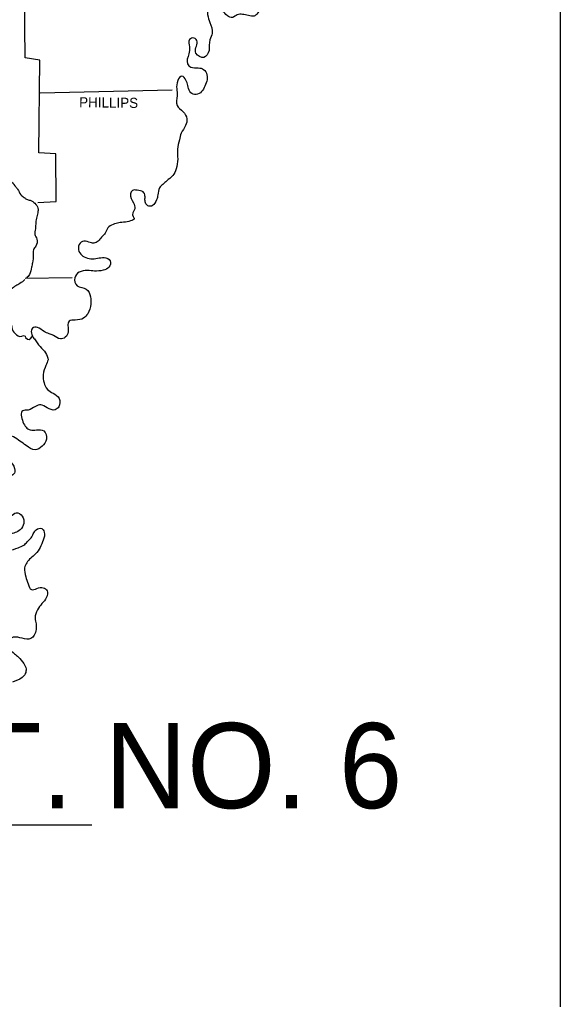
# Model space of a CAD drawing. Extents: x 22866 to 28196, y 1324810 to 1328105.
# Drawn here: x 26814.2 to 27045.6, y 1326588.3 to 1327007.4 of the extents above; entities that cross this region are included whole.
import ezdxf

# ---------------------------------------------------------------- set-up
doc = ezdxf.new("R2010")
doc.units = 0
for name, color, linetype in [('Default', 7, 'Continuous'), ('Level 2', 7, 'Continuous'), ('R_Border', 7, 'Continuous'), ('R_Draft', 7, 'Continuous')]:
    doc.layers.add(name, color=color, linetype=linetype)

msp = doc.modelspace()

# ---------------------------------------------------------------- linework, layer by layer
at = {"layer": 'Default'}
msp.add_line((26431.16, 1326662.93), (26845.06, 1326662.93), dxfattribs=at)
at = {"layer": 'R_Border'}
msp.add_line((27045.59, 1325448.4), (27045.59, 1327502.95), dxfattribs=at)
at = {"layer": 'R_Draft'}
msp.add_line((26816.65, 1326896.78), (26836.65, 1326897.08), dxfattribs=at)
for points in [[(26822.05, 1326929.08), (26829.85, 1326929.58), (26829.75, 1326949.88), (26822.45, 1326950.38), (26822.85, 1326990.08), (26816.55, 1326990.98), (26816.35, 1327017.68), (26901.65, 1327018.28)], [(26823.05, 1326975.98), (26879.45, 1326977.38)], [(26814.25, 1326871.88), (26815.15, 1326871.95), (26815.82, 1326872.25), (26816.57, 1326872.01), (26816.79, 1326871.36), (26817.52, 1326870.66), (26818.36, 1326870.56), (26818.96, 1326871.05), (26819.61, 1326871.88)]]:
    msp.add_lwpolyline(points, dxfattribs=at)
for points in [[(26938.75, 1327093.18), (26939.15, 1327090.28), (26937.45, 1327087.18), (26936.85, 1327084.08), (26937.15, 1327080.98), (26933.95, 1327079.28), (26931.15, 1327077.28), (26932.75, 1327074.88), (26935.75, 1327072.68), (26938.75, 1327070.98), (26940.65, 1327069.28), (26941.15, 1327065.18), (26941.65, 1327062.58), (26942.65, 1327058.98), (26943.05, 1327056.48), (26941.25, 1327053.48), (26939.15, 1327052.88), (26936.95, 1327053.58), (26934.35, 1327053.78), (26932.25, 1327051.78), (26930.75, 1327048.98), (26929.25, 1327046.18), (26928.15, 1327043.78), (26927.05, 1327041.18), (26924.85, 1327038.18), (26922.15, 1327037.68), (26918.95, 1327036.88), (26917.05, 1327034.68), (26917.35, 1327030.98), (26919.15, 1327028.48), (26920.55, 1327025.38), (26921.55, 1327022.68), (26921.05, 1327019.28), (26919.65, 1327016.78), (26917.85, 1327015.28), (26917.05, 1327012.08), (26915.75, 1327009.68), (26914.55, 1327008.88), (26912.15, 1327009.08), (26909.55, 1327009.58), (26907.35, 1327009.38), (26905.25, 1327008.28), (26903.15, 1327008.98), (26900.95, 1327011.38), (26899.15, 1327013.18), (26897.15, 1327013.88), (26895.05, 1327012.78), (26894.65, 1327009.48), (26895.65, 1327006.08), (26896.55, 1327001.48), (26895.65, 1326998.68), (26895.35, 1326994.08)], [(26895.35, 1326994.08), (26893.05, 1326991.18), (26889.65, 1326992.98), (26889.65, 1326995.38), (26890.15, 1326997.88), (26888.95, 1326999.48), (26886.85, 1326998.78), (26886.85, 1326995.68), (26886.65, 1326992.68), (26886.05, 1326988.38), (26887.45, 1326987.08), (26890.65, 1326986.68), (26892.95, 1326986.08), (26894.35, 1326983.78), (26894.25, 1326980.98), (26893.15, 1326978.28), (26891.55, 1326976.08), (26889.05, 1326975.28), (26887.05, 1326976.58), (26886.25, 1326979.18), (26885.35, 1326981.48), (26883.65, 1326983.18), (26881.85, 1326981.28), (26881.45, 1326977.78), (26881.55, 1326974.78), (26881.55, 1326970.68), (26884.15, 1326967.98), (26885.75, 1326964.88), (26885.25, 1326962.08), (26883.35, 1326958.78), (26882.55, 1326955.88), (26881.75, 1326951.98), (26881.85, 1326947.68), (26881.15, 1326943.48), (26879.75, 1326940.68), (26877.15, 1326938.38), (26875.45, 1326936.88), (26874.05, 1326935.38), (26873.35, 1326932.38), (26872.85, 1326930.28), (26870.95, 1326927.78), (26869.45, 1326927.58), (26868.25, 1326928.58), (26867.85, 1326930.28), (26867.85, 1326931.98), (26867.05, 1326933.68), (26864.55, 1326934.38), (26862.55, 1326934.28), (26861.65, 1326932.88), (26862.95, 1326928.98), (26863.45, 1326926.48), (26862.75, 1326923.08), (26863.15, 1326922.68), (26859.55, 1326920.78), (26856.65, 1326920.48), (26854.25, 1326919.78), (26851.95, 1326918.28), (26850.85, 1326916.08), (26849.25, 1326914.28), (26847.85, 1326912.58), (26845.95, 1326911.78), (26843.85, 1326912.18), (26841.05, 1326912.48), (26839.45, 1326910.48), (26839.95, 1326907.58), (26841.85, 1326905.88), (26844.65, 1326905.08), (26847.55, 1326905.28), (26850.35, 1326905.58), (26852.95, 1326904.18), (26852.45, 1326901.48), (26849.95, 1326900.18), (26846.25, 1326899.78), (26843.25, 1326900.08), (26839.65, 1326899.28), (26837.85, 1326896.98), (26838.85, 1326893.48), (26842.75, 1326892.08), (26844.55, 1326888.78), (26844.65, 1326885.68), (26843.35, 1326881.58), (26841.55, 1326879.68), (26838.05, 1326878.88), (26835.35, 1326878.38), (26834.95, 1326873.78), (26833.75, 1326871.48), (26831.65, 1326870.78), (26828.65, 1326872.28), (26826.85, 1326872.98), (26824.65, 1326873.98), (26821.85, 1326875.68), (26819.75, 1326875.38), (26820.35, 1326870.98), (26820.55, 1326870.78), (26822.95, 1326867.48), (26825.35, 1326864.88), (26826.45, 1326861.78)], [(26791.75, 1326961.88), (26792.05, 1326957.78), (26794.45, 1326957.18), (26795.45, 1326956.08), (26795.95, 1326953.78), (26797.65, 1326952.78), (26799.95, 1326951.38), (26801.35, 1326950.38), (26802.35, 1326948.78), (26802.95, 1326946.18), (26804.55, 1326944.48), (26806.75, 1326943.68), (26808.35, 1326941.78), (26809.35, 1326939.08), (26810.95, 1326937.88), (26812.55, 1326935.78), (26813.35, 1326934.88), (26814.75, 1326932.48), (26816.15, 1326931.28), (26817.15, 1326930.58), (26818.75, 1326930.08), (26820.75, 1326928.78), (26822.05, 1326926.78), (26822.05, 1326925.28), (26821.55, 1326922.98), (26821.15, 1326920.58), (26820.95, 1326917.88), (26820.75, 1326915.48), (26821.65, 1326913.48), (26821.15, 1326910.48), (26820.15, 1326908.88), (26820.05, 1326906.68), (26819.75, 1326903.38), (26819.35, 1326901.48), (26818.45, 1326898.38), (26817.15, 1326896.78)], [(26816.45, 1326896.18), (26814.35, 1326894.48), (26812.55, 1326893.48), (26810.65, 1326892.08), (26808.35, 1326890.38), (26807.25, 1326887.48), (26806.65, 1326883.48), (26807.45, 1326881.08), (26809.25, 1326878.98), (26810.45, 1326877.28), (26811.35, 1326874.28), (26813.55, 1326872.18), (26814.25, 1326871.88)], [(26826.45, 1326861.78), (26825.45, 1326859.48), (26824.35, 1326855.48), (26824.65, 1326852.08), (26826.15, 1326849.18), (26828.55, 1326847.58), (26831.15, 1326845.28), (26830.95, 1326841.78), (26829.45, 1326840.48), (26825.95, 1326841.38), (26823.25, 1326842.58), (26820.95, 1326841.88), (26817.85, 1326840.38), (26815.55, 1326840.08), (26815.65, 1326835.28), (26818.75, 1326831.88), (26821.45, 1326831.88), (26824.55, 1326831.48), (26825.65, 1326827.88), (26823.85, 1326824.88), (26820.85, 1326823.38), (26817.05, 1326825.18), (26814.35, 1326827.08), (26811.65, 1326828.88), (26808.25, 1326829.78), (26806.35, 1326829.38), (26805.45, 1326825.18), (26807.05, 1326821.38), (26809.65, 1326818.78), (26812.05, 1326815.38), (26811.65, 1326812.88), (26809.85, 1326812.18), (26806.65, 1326811.48), (26804.75, 1326810.48), (26804.25, 1326809.68), (26805.25, 1326806.28), (26806.15, 1326802.58), (26806.15, 1326799.78), (26805.05, 1326797.18), (26803.35, 1326793.18), (26803.55, 1326790.58), (26804.75, 1326789.38), (26806.25, 1326789.78), (26808.25, 1326791.18), (26809.55, 1326792.78), (26810.65, 1326794.78), (26812.75, 1326796.48), (26815.35, 1326794.98), (26815.95, 1326791.88), (26814.45, 1326789.18), (26812.35, 1326787.98), (26809.75, 1326786.98), (26807.85, 1326784.78), (26808.35, 1326782.18), (26809.85, 1326780.78), (26813.55, 1326781.48), (26816.05, 1326782.58), (26817.45, 1326783.98), (26819.15, 1326785.68), (26820.05, 1326787.38), (26821.35, 1326789.18), (26823.65, 1326789.68), (26824.75, 1326788.18), (26824.35, 1326784.78), (26822.95, 1326781.58), (26821.05, 1326778.88), (26818.95, 1326776.98), (26816.35, 1326772.88), (26816.85, 1326769.08), (26817.85, 1326765.98), (26819.25, 1326763.58), (26821.65, 1326764.08), (26824.35, 1326764.38), (26825.95, 1326763.08), (26825.75, 1326760.28), (26823.75, 1326757.58), (26821.85, 1326754.98), (26820.85, 1326751.38), (26821.25, 1326748.88), (26821.25, 1326746.58), (26820.45, 1326744.08), (26819.05, 1326742.68), (26815.35, 1326742.78), (26811.45, 1326743.18), (26809.35, 1326741.98), (26809.75, 1326738.58), (26812.05, 1326736.08), (26813.65, 1326734.78), (26815.95, 1326731.98), (26816.95, 1326729.68), (26816.65, 1326727.68), (26815.25, 1326725.98), (26811.15, 1326723.98)]]:
    msp.add_spline(points, degree=3, dxfattribs=at)

# ---------------------------------------------------------------- texts
at = {"layer": 'Level 2'}
msp.add_text('ARK. HWY. DIST. NO. 6', height=36.436, dxfattribs=at).set_placement((26444.61, 1326670.1))
at = {"layer": 'R_Draft'}
msp.add_text('PHILLIPS', height=4.3, rotation=359.3179, dxfattribs=at).set_placement((26839.65, 1326969.88))

doc.saveas('drawing.dxf')
